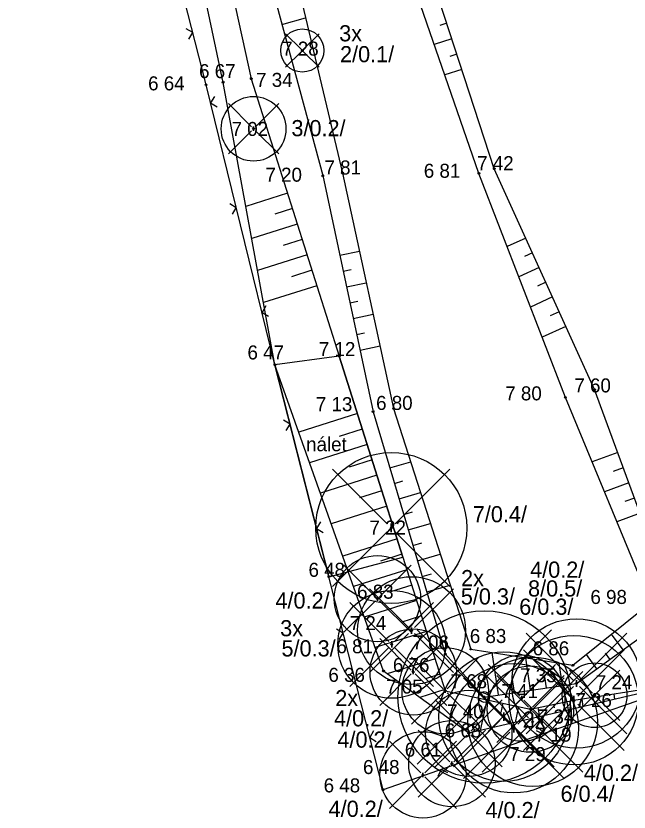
# Model space of a CAD drawing. Extents: x -684336 to -684039, y -993109 to -992688.
# Drawn here: x -684280.1 to -684251.69, y -992904.14 to -992867.21 of the extents above; entities that cross this region are included whole.
import ezdxf

# ---------------------------------------------------------------- set-up
doc = ezdxf.new("R2010")
doc.units = 0
for name, color, linetype in [('51', 7, 'Continuous'), ('57', 7, 'Continuous'), ('60', 7, 'Continuous'), ('70', 7, 'Continuous')]:
    doc.layers.add(name, color=color, linetype=linetype)

msp = doc.modelspace()

# ---------------------------------------------------------------- linework, layer by layer
at = {"layer": '51'}
for points in [[(-684227.21, -992890.21), (-684237.13, -992893.77), (-684248.6, -992898.04), (-684263.09, -992903.1), (-684268.1, -992883.39), (-684271.29, -992870.41), (-684274.7, -992857.04), (-684277.74, -992844.67), (-684280.1, -992835.85), (-684277.64, -992831.2), (-684264.34, -992827.86), (-684252.53, -992824.88)], [(-684248.6, -992898.04), (-684259.12, -992900.48), (-684263.07, -992897.6), (-684268.1, -992883.39), (-684270.5, -992870.3), (-684273.42, -992856.49), (-684276.84, -992844.62), (-684278.77, -992835.66), (-684276.49, -992831.3), (-684269.75, -992830.75), (-684275.57, -992832.23), (-684276.67, -992834.45), (-684274.82, -992844.3), (-684272.25, -992856.25), (-684269.2, -992870.13), (-684265.12, -992882.99), (-684260.21, -992898.51), (-684256.26, -992899.36), (-684254.25, -992898.95), (-684248.751, -992898.075)], [(-684272.088, -992868.292), (-684271.908, -992867.988), (-684272.212, -992867.807)], [(-684270.9, -992870.949), (-684271.083, -992871.251), (-684270.781, -992871.434)], [(-684270.073, -992876.409), (-684269.89, -992876.107), (-684270.192, -992875.924)], [(-684268.514, -992880.66), (-684268.697, -992880.962), (-684268.394, -992881.145)], [(-684267.582, -992886.443), (-684267.401, -992886.139), (-684267.705, -992885.959)], [(-684265.989, -992890.681), (-684266.169, -992890.985), (-684265.866, -992891.166)], [(-684265.118, -992896.135), (-684264.938, -992895.831), (-684265.242, -992895.65)], [(-684255.999, -992900.359), (-684255.681, -992900.513), (-684255.527, -992900.194)], [(-684263.525, -992900.373), (-684263.706, -992900.677), (-684263.402, -992900.858)], [(-684260.083, -992902.315), (-684260.401, -992902.161), (-684260.555, -992902.479)]]:
    msp.add_lwpolyline(points, dxfattribs=at)
for points in [[(-684268.27, -992833.23), (-684270.44, -992832.08), (-684274.11, -992832.95), (-684275.43, -992835.26), (-684273, -992846.66), (-684269.84, -992859.98), (-684265.88, -992874.62), (-684263.55, -992885.57), (-684260.21, -992896.8), (-684258.4, -992898.8), (-684254.13, -992898.17), (-684249.51, -992894.83), (-684253.29, -992884.54), (-684257.94, -992874.3), (-684263.02, -992858.7), (-684266.06, -992847.54)], [(-684269.72, -992835.11), (-684273.83, -992835.79), (-684272.03, -992846.57), (-684268.48, -992859.73), (-684264.97, -992874.5), (-684262.6, -992885.42), (-684259.03, -992896.58), (-684254.29, -992897.33), (-684250.7, -992894.43), (-684254.64, -992884.91), (-684258.65, -992874.52), (-684264.18, -992858.51), (-684267.32, -992848.18)]]:
    msp.add_lwpolyline(points, close=True, dxfattribs=at)
at = {"layer": '57'}
for points in [[(-684266.807, -992868.782), (-684266.785, -992868.82), (-684266.807, -992868.857), (-684266.852, -992868.857), (-684266.875, -992868.82), (-684266.852, -992868.782)], [(-684271.268, -992870.373), (-684271.245, -992870.41), (-684271.268, -992870.448), (-684271.312, -992870.448), (-684271.335, -992870.41), (-684271.312, -992870.373)], [(-684270.478, -992870.263), (-684270.455, -992870.3), (-684270.478, -992870.338), (-684270.522, -992870.338), (-684270.545, -992870.3), (-684270.522, -992870.263)], [(-684269.177, -992870.093), (-684269.155, -992870.13), (-684269.177, -992870.167), (-684269.222, -992870.167), (-684269.245, -992870.13), (-684269.222, -992870.093)], [(-684269.068, -992872.412), (-684269.045, -992872.45), (-684269.068, -992872.487), (-684269.113, -992872.487), (-684269.135, -992872.45), (-684269.113, -992872.412)], [(-684264.948, -992874.463), (-684264.925, -992874.5), (-684264.948, -992874.537), (-684264.992, -992874.537), (-684265.015, -992874.5), (-684264.992, -992874.463)], [(-684258.628, -992874.483), (-684258.605, -992874.52), (-684258.628, -992874.557), (-684258.673, -992874.557), (-684258.695, -992874.52), (-684258.673, -992874.483)], [(-684257.917, -992874.263), (-684257.895, -992874.3), (-684257.917, -992874.338), (-684257.962, -992874.338), (-684257.985, -992874.3), (-684257.962, -992874.263)], [(-684265.858, -992874.583), (-684265.835, -992874.62), (-684265.858, -992874.657), (-684265.903, -992874.657), (-684265.925, -992874.62), (-684265.903, -992874.583)], [(-684265.097, -992882.952), (-684265.075, -992882.99), (-684265.097, -992883.027), (-684265.142, -992883.027), (-684265.165, -992882.99), (-684265.142, -992882.952)], [(-684268.077, -992883.353), (-684268.055, -992883.39), (-684268.077, -992883.427), (-684268.122, -992883.427), (-684268.145, -992883.39), (-684268.122, -992883.353)], [(-684253.268, -992884.503), (-684253.245, -992884.54), (-684253.268, -992884.578), (-684253.312, -992884.578), (-684253.335, -992884.54), (-684253.312, -992884.503)], [(-684254.617, -992884.873), (-684254.595, -992884.91), (-684254.617, -992884.948), (-684254.662, -992884.948), (-684254.685, -992884.91), (-684254.662, -992884.873)], [(-684263.528, -992885.532), (-684263.505, -992885.57), (-684263.528, -992885.607), (-684263.573, -992885.607), (-684263.595, -992885.57), (-684263.573, -992885.532)], [(-684262.577, -992885.383), (-684262.555, -992885.42), (-684262.577, -992885.458), (-684262.622, -992885.458), (-684262.645, -992885.42), (-684262.622, -992885.383)], [(-684262.688, -992890.922), (-684262.665, -992890.96), (-684262.688, -992890.997), (-684262.732, -992890.997), (-684262.755, -992890.96), (-684262.732, -992890.922)], [(-684265.578, -992893.187), (-684265.555, -992893.225), (-684265.578, -992893.262), (-684265.623, -992893.262), (-684265.645, -992893.225), (-684265.623, -992893.187)], [(-684263.327, -992894.202), (-684263.305, -992894.24), (-684263.327, -992894.277), (-684263.372, -992894.277), (-684263.395, -992894.24), (-684263.372, -992894.202)], [(-684261.748, -992895.682), (-684261.725, -992895.72), (-684261.748, -992895.758), (-684261.792, -992895.758), (-684261.815, -992895.72), (-684261.792, -992895.682)], [(-684262.667, -992896.323), (-684262.645, -992896.36), (-684262.667, -992896.397), (-684262.712, -992896.397), (-684262.735, -992896.36), (-684262.712, -992896.323)], [(-684259.008, -992896.542), (-684258.985, -992896.58), (-684259.008, -992896.617), (-684259.052, -992896.617), (-684259.075, -992896.58), (-684259.052, -992896.542)], [(-684260.188, -992896.763), (-684260.165, -992896.8), (-684260.188, -992896.838), (-684260.232, -992896.838), (-684260.255, -992896.8), (-684260.232, -992896.763)], [(-684254.268, -992897.292), (-684254.245, -992897.33), (-684254.268, -992897.367), (-684254.312, -992897.367), (-684254.335, -992897.33), (-684254.312, -992897.292)], [(-684263.047, -992897.562), (-684263.025, -992897.6), (-684263.047, -992897.638), (-684263.093, -992897.638), (-684263.115, -992897.6), (-684263.093, -992897.562)], [(-684261.667, -992897.603), (-684261.645, -992897.64), (-684261.667, -992897.677), (-684261.712, -992897.677), (-684261.735, -992897.64), (-684261.712, -992897.603)], [(-684260.188, -992898.473), (-684260.165, -992898.51), (-684260.188, -992898.548), (-684260.232, -992898.548), (-684260.255, -992898.51), (-684260.232, -992898.473)], [(-684254.108, -992898.133), (-684254.085, -992898.17), (-684254.108, -992898.208), (-684254.153, -992898.208), (-684254.175, -992898.17), (-684254.153, -992898.133)], [(-684258.378, -992898.763), (-684258.355, -992898.8), (-684258.378, -992898.838), (-684258.423, -992898.838), (-684258.445, -992898.8), (-684258.423, -992898.763)], [(-684256.638, -992898.812), (-684256.615, -992898.85), (-684256.638, -992898.888), (-684256.682, -992898.888), (-684256.705, -992898.85), (-684256.682, -992898.812)], [(-684253.268, -992898.682), (-684253.245, -992898.72), (-684253.268, -992898.758), (-684253.312, -992898.758), (-684253.335, -992898.72), (-684253.312, -992898.682)], [(-684254.228, -992898.912), (-684254.205, -992898.95), (-684254.228, -992898.987), (-684254.272, -992898.987), (-684254.295, -992898.95), (-684254.272, -992898.912)], [(-684256.238, -992899.323), (-684256.215, -992899.36), (-684256.238, -992899.397), (-684256.282, -992899.397), (-684256.305, -992899.36), (-684256.282, -992899.323)], [(-684257.478, -992899.672), (-684257.455, -992899.71), (-684257.478, -992899.747), (-684257.522, -992899.747), (-684257.545, -992899.71), (-684257.522, -992899.672)], [(-684256.138, -992899.912), (-684256.115, -992899.95), (-684256.138, -992899.987), (-684256.182, -992899.987), (-684256.205, -992899.95), (-684256.182, -992899.912)], [(-684257.008, -992900.213), (-684256.985, -992900.25), (-684257.008, -992900.287), (-684257.052, -992900.287), (-684257.075, -992900.25), (-684257.052, -992900.213)], [(-684259.097, -992900.443), (-684259.075, -992900.48), (-684259.097, -992900.518), (-684259.142, -992900.518), (-684259.165, -992900.48), (-684259.142, -992900.443)], [(-684259.878, -992901.853), (-684259.855, -992901.89), (-684259.878, -992901.927), (-684259.923, -992901.927), (-684259.945, -992901.89), (-684259.923, -992901.853)], [(-684261.218, -992902.373), (-684261.195, -992902.41), (-684261.218, -992902.448), (-684261.263, -992902.448), (-684261.285, -992902.41), (-684261.263, -992902.373)], [(-684263.068, -992903.062), (-684263.045, -992903.1), (-684263.068, -992903.138), (-684263.113, -992903.138), (-684263.135, -992903.1), (-684263.113, -992903.062)]]:
    msp.add_lwpolyline(points, close=True, dxfattribs=at)
at = {"layer": '60'}
for points in [[(-684266.876, -992868.774), (-684267.608, -992868.042)], [(-684266.784, -992868.774), (-684266.052, -992868.042)], [(-684266.876, -992868.866), (-684267.608, -992869.598)], [(-684266.83, -992868.77), (-684266.83, -992868.87), (-684266.83, -992868.77)], [(-684266.784, -992868.866), (-684266.052, -992869.598)], [(-684269.182, -992872.358), (-684270.257, -992871.283)], [(-684268.998, -992872.358), (-684267.923, -992871.283)], [(-684269.182, -992872.542), (-684270.257, -992873.617)], [(-684269.09, -992872.35), (-684269.09, -992872.55), (-684269.09, -992872.35)], [(-684268.998, -992872.542), (-684267.923, -992873.617)], [(-684262.894, -992890.776), (-684265.432, -992888.238)], [(-684262.526, -992890.776), (-684259.988, -992888.238)], [(-684262.71, -992890.76), (-684262.71, -992891.16), (-684262.71, -992890.76)], [(-684262.894, -992891.144), (-684265.432, -992893.682)], [(-684262.526, -992891.144), (-684259.988, -992893.682)], [(-684263.442, -992894.148), (-684264.906, -992892.684)], [(-684263.258, -992894.148), (-684261.794, -992892.684)], [(-684261.908, -992895.582), (-684263.715, -992893.775)], [(-684261.632, -992895.582), (-684259.825, -992893.775)], [(-684263.442, -992894.332), (-684264.906, -992895.796)], [(-684262.828, -992896.222), (-684264.635, -992894.415)], [(-684263.35, -992894.14), (-684263.35, -992894.34), (-684263.35, -992894.14)], [(-684263.258, -992894.332), (-684261.794, -992895.796)], [(-684262.552, -992896.222), (-684260.745, -992894.415)], [(-684261.908, -992895.858), (-684263.715, -992897.665)], [(-684261.77, -992895.57), (-684261.77, -992895.87), (-684261.77, -992895.57)], [(-684261.632, -992895.858), (-684259.825, -992897.665)], [(-684258.63, -992898.57), (-684261.511, -992895.689)], [(-684258.17, -992898.57), (-684255.289, -992895.689)], [(-684254.268, -992898.032), (-684256.463, -992895.837)], [(-684253.992, -992898.032), (-684251.797, -992895.837)], [(-684261.782, -992897.548), (-684263.246, -992896.084)], [(-684262.69, -992896.21), (-684262.69, -992896.51), (-684262.69, -992896.21)], [(-684261.598, -992897.548), (-684260.134, -992896.084)], [(-684262.828, -992896.498), (-684264.635, -992898.305)], [(-684262.552, -992896.498), (-684260.745, -992898.305)], [(-684254.434, -992898.766), (-684256.583, -992896.617)], [(-684254.066, -992898.766), (-684251.917, -992896.617)], [(-684260.302, -992898.418), (-684261.766, -992896.954)], [(-684260.118, -992898.418), (-684258.654, -992896.954)], [(-684257.684, -992899.526), (-684259.833, -992897.377)], [(-684256.752, -992898.758), (-684258.216, -992897.294)], [(-684257.316, -992899.526), (-684255.167, -992897.377)], [(-684256.568, -992898.758), (-684255.104, -992897.294)], [(-684261.782, -992897.732), (-684263.246, -992899.196)], [(-684261.69, -992897.54), (-684261.69, -992897.74), (-684261.69, -992897.54)], [(-684261.598, -992897.732), (-684260.134, -992899.196)], [(-684256.344, -992899.766), (-684258.493, -992897.617)], [(-684255.976, -992899.766), (-684253.827, -992897.617)], [(-684253.382, -992898.628), (-684254.457, -992897.553)], [(-684253.198, -992898.628), (-684252.123, -992897.553)], [(-684257.214, -992900.066), (-684259.363, -992897.917)], [(-684256.352, -992899.268), (-684257.816, -992897.804)], [(-684256.846, -992900.066), (-684254.697, -992897.917)], [(-684256.168, -992899.268), (-684254.704, -992897.804)], [(-684254.13, -992898.02), (-684254.13, -992898.32), (-684254.13, -992898.02)], [(-684260.21, -992898.41), (-684260.21, -992898.61), (-684260.21, -992898.41)], [(-684254.268, -992898.308), (-684256.463, -992900.503)], [(-684253.992, -992898.308), (-684251.797, -992900.503)], [(-684260.302, -992898.602), (-684261.766, -992900.066)], [(-684260.118, -992898.602), (-684258.654, -992900.066)], [(-684256.66, -992898.75), (-684256.66, -992898.95), (-684256.66, -992898.75)], [(-684253.382, -992898.812), (-684254.457, -992899.887)], [(-684254.25, -992898.75), (-684254.25, -992899.15), (-684254.25, -992898.75)], [(-684253.29, -992898.62), (-684253.29, -992898.82), (-684253.29, -992898.62)], [(-684253.198, -992898.812), (-684252.123, -992899.887)], [(-684258.63, -992899.03), (-684261.511, -992901.911)], [(-684259.212, -992900.388), (-684260.676, -992898.924)], [(-684259.028, -992900.388), (-684257.564, -992898.924)], [(-684256.752, -992898.942), (-684258.216, -992900.406)], [(-684258.17, -992899.03), (-684255.289, -992901.911)], [(-684254.434, -992899.134), (-684256.583, -992901.283)], [(-684256.568, -992898.942), (-684255.104, -992900.406)], [(-684254.066, -992899.134), (-684251.917, -992901.283)], [(-684256.352, -992899.452), (-684257.816, -992900.916)], [(-684257.5, -992899.51), (-684257.5, -992899.91), (-684257.5, -992899.51)], [(-684256.26, -992899.26), (-684256.26, -992899.46), (-684256.26, -992899.26)], [(-684256.168, -992899.452), (-684254.704, -992900.916)], [(-684257.684, -992899.894), (-684259.833, -992902.043)], [(-684257.316, -992899.894), (-684255.167, -992902.043)], [(-684256.16, -992899.75), (-684256.16, -992900.15), (-684256.16, -992899.75)], [(-684259.992, -992901.798), (-684261.456, -992900.334)], [(-684259.808, -992901.798), (-684258.344, -992900.334)], [(-684256.344, -992900.134), (-684258.493, -992902.283)], [(-684257.03, -992900.05), (-684257.03, -992900.45), (-684257.03, -992900.05)], [(-684255.976, -992900.134), (-684253.827, -992902.283)], [(-684259.212, -992900.572), (-684260.676, -992902.036)], [(-684257.214, -992900.434), (-684259.363, -992902.583)], [(-684259.12, -992900.38), (-684259.12, -992900.58), (-684259.12, -992900.38)], [(-684259.028, -992900.572), (-684257.564, -992902.036)], [(-684256.846, -992900.434), (-684254.697, -992902.583)], [(-684261.332, -992902.318), (-684262.796, -992900.854)], [(-684261.148, -992902.318), (-684259.684, -992900.854)], [(-684259.9, -992901.79), (-684259.9, -992901.99), (-684259.9, -992901.79)], [(-684259.992, -992901.982), (-684261.456, -992903.446)], [(-684259.808, -992901.982), (-684258.344, -992903.446)], [(-684261.332, -992902.502), (-684262.796, -992903.966)], [(-684261.24, -992902.31), (-684261.24, -992902.51), (-684261.24, -992902.31)], [(-684261.148, -992902.502), (-684259.684, -992903.966)]]:
    msp.add_lwpolyline(points, dxfattribs=at)
msp.add_lwpolyline([(-684265.6, -992893.225), (-684262.171, -992892.311), (-684265.12, -992882.99), (-684268.1, -992883.39)], close=True, dxfattribs=at)
for centre, radius in [((-684266.83, -992868.82), 1), ((-684269.09, -992872.45), 1.5), ((-684262.71, -992890.96), 3.5), ((-684263.35, -992894.24), 2), ((-684261.77, -992895.72), 2.5), ((-684262.69, -992896.36), 2.5), ((-684258.4, -992898.8), 4), ((-684254.13, -992898.17), 3), ((-684261.69, -992897.64), 2), ((-684254.25, -992898.95), 3), ((-684260.21, -992898.51), 2), ((-684257.5, -992899.71), 3), ((-684256.16, -992899.95), 3), ((-684256.66, -992898.85), 2), ((-684257.03, -992900.25), 3), ((-684256.26, -992899.36), 2), ((-684253.29, -992898.72), 1.5), ((-684259.12, -992900.48), 2), ((-684258.4, -992898.8), 0.25), ((-684259.9, -992901.89), 2), ((-684261.24, -992902.41), 2)]:
    msp.add_circle(centre, radius, dxfattribs=at)
at = {"layer": '70'}
for points in [[(-684267.777, -992867.608), (-684266.678, -992867.311)], [(-684260.135, -992867.558), (-684260.466, -992867.666)], [(-684259.903, -992868.271), (-684260.717, -992868.536)], [(-684259.671, -992868.984), (-684259.991, -992869.089)], [(-684259.439, -992869.698), (-684260.227, -992869.954)], [(-684267.516, -992875.437), (-684269.446, -992876.049)], [(-684267.289, -992876.152), (-684268.097, -992876.408)], [(-684267.063, -992876.867), (-684269.173, -992877.537)], [(-684266.836, -992877.582), (-684267.716, -992877.861)], [(-684256.479, -992877.517), (-684257.342, -992877.909)], [(-684265.094, -992878.315), (-684264.184, -992878.121)], [(-684266.609, -992878.297), (-684268.901, -992879.024)], [(-684256.169, -992878.2), (-684256.53, -992878.364)], [(-684255.859, -992878.883), (-684256.801, -992879.311)], [(-684266.382, -992879.012), (-684267.335, -992879.314)], [(-684264.938, -992879.048), (-684264.573, -992878.971)], [(-684264.782, -992879.782), (-684263.866, -992879.587)], [(-684255.549, -992879.566), (-684255.941, -992879.744)], [(-684266.155, -992879.726), (-684268.628, -992880.511)], [(-684255.239, -992880.249), (-684256.26, -992880.713)], [(-684264.626, -992880.515), (-684264.258, -992880.437)], [(-684264.469, -992881.249), (-684263.548, -992881.053)], [(-684254.928, -992880.932), (-684255.353, -992881.125)], [(-684254.618, -992881.615), (-684255.719, -992882.115)], [(-684264.313, -992881.983), (-684263.943, -992881.904)], [(-684264.157, -992882.716), (-684263.23, -992882.519)], [(-684264.276, -992885.658), (-684266.993, -992886.517)], [(-684264.05, -992886.373), (-684265.127, -992886.714)], [(-684263.824, -992887.088), (-684266.492, -992887.932)], [(-684252.217, -992887.461), (-684253.404, -992887.897)], [(-684263.597, -992887.803), (-684264.655, -992888.138)], [(-684262.775, -992888.177), (-684261.81, -992887.89)], [(-684263.371, -992888.518), (-684265.991, -992889.347)], [(-684251.959, -992888.165), (-684252.422, -992888.335)], [(-684262.561, -992888.896), (-684262.169, -992888.779)], [(-684251.7, -992888.869), (-684252.83, -992889.284)], [(-684263.145, -992889.233), (-684264.183, -992889.562)], [(-684262.347, -992889.615), (-684261.353, -992889.319)], [(-684251.441, -992889.573), (-684251.882, -992889.734)], [(-684262.919, -992889.948), (-684265.49, -992890.762)], [(-684262.133, -992890.334), (-684261.73, -992890.214)], [(-684251.183, -992890.277), (-684252.256, -992890.671)], [(-684261.919, -992891.053), (-684260.896, -992890.748)], [(-684262.439, -992891.464), (-684264.96, -992892.261)], [(-684261.706, -992891.771), (-684261.29, -992891.648)], [(-684262.213, -992892.179), (-684263.212, -992892.495)], [(-684261.492, -992892.49), (-684260.438, -992892.177)], [(-684261.987, -992892.894), (-684264.459, -992893.676)], [(-684261.278, -992893.209), (-684260.851, -992893.082)], [(-684261.761, -992893.609), (-684262.74, -992893.919)], [(-684261.064, -992893.928), (-684259.981, -992893.606)], [(-684261.534, -992894.324), (-684263.958, -992895.091)], [(-684261.308, -992895.039), (-684262.268, -992895.343)], [(-684261.082, -992895.754), (-684263.457, -992896.506)], [(-684251.971, -992896.609), (-684252.497, -992895.882)], [(-684257.743, -992898.703), (-684258.033, -992896.738)], [(-684256.259, -992898.484), (-684256.48, -992896.983)], [(-684253.187, -992897.488), (-684253.666, -992896.826)], [(-684252.579, -992897.049), (-684252.78, -992896.771)], [(-684260.679, -992897.026), (-684262.896, -992897.727)], [(-684254.775, -992898.265), (-684254.928, -992897.229)], [(-684260.453, -992897.741), (-684261.129, -992897.955)], [(-684257.001, -992898.594), (-684257.103, -992897.9)], [(-684255.517, -992898.375), (-684255.592, -992897.867)], [(-684260.227, -992898.456), (-684261.391, -992898.824)], [(-684253.145, -992898.774), (-684253.125, -992898.898)], [(-684252.404, -992898.656), (-684252.364, -992898.913)], [(-684258.278, -992898.926), (-684258.586, -992900.356)], [(-684257.545, -992899.083), (-684257.639, -992899.518)], [(-684255.19, -992899.142), (-684255.157, -992899.305)], [(-684254.455, -992898.992), (-684254.376, -992899.38)], [(-684253.886, -992898.892), (-684253.828, -992899.253)], [(-684256.812, -992899.241), (-684256.971, -992899.982)], [(-684255.925, -992899.292), (-684255.838, -992899.719)]]:
    msp.add_lwpolyline(points, dxfattribs=at)

# ---------------------------------------------------------------- texts
at = {"layer": '57'}
for s, p in [('7 28', (-684267.764, -992869.057)), ('6 67', (-684271.615, -992870.1)), ('6 64', (-684273.976, -992870.666)), ('7 34', (-684268.973, -992870.505)), ('7 02', (-684270.109, -992872.782)), ('7 42', (-684258.73, -992874.368)), ('7 81', (-684265.804, -992874.568)), ('6 81', (-684261.202, -992874.72)), ('7 20', (-684268.539, -992874.903)), ('6 47', (-684269.372, -992883.145)), ('7 12', (-684266.064, -992882.99)), ('7 60', (-684254.226, -992884.675)), ('7 80', (-684257.427, -992885.042)), ('6 80', (-684263.412, -992885.486)), ('7 13', (-684266.204, -992885.544)), ('7 22', (-684263.719, -992891.268)), ('6 48', (-684266.544, -992893.225)), ('6 83', (-684264.294, -992894.24)), ('6 98', (-684253.482, -992894.485)), ('7 24', (-684264.635, -992895.695)), ('6 83', (-684259.069, -992896.295)), ('6 81', (-684265.25, -992896.77)), ('7 06', (-684261.727, -992896.595)), ('6 86', (-684256.156, -992896.866)), ('6 76', (-684262.634, -992897.64)), ('6 36', (-684265.623, -992898.096)), ('7 68', (-684259.964, -992898.393)), ('7 35', (-684256.74, -992898.116)), ('7 05', (-684262.95, -992898.641)), ('7 24', (-684253.233, -992898.442)), ('7 41', (-684257.604, -992898.85)), ('7 26', (-684254.179, -992899.269)), ('7 40', (-684260.121, -992899.793)), ('7 34', (-684255.92, -992900.028)), ('6 68', (-684260.231, -992900.672)), ('7 19', (-684256.046, -992900.87)), ('6 61', (-684262.081, -992901.565)), ('7 29', (-684257.244, -992901.772)), ('6 48', (-684264.019, -992902.371)), ('6 48', (-684265.842, -992903.222))]:
    msp.add_text(s, height=0.65, dxfattribs=at).set_placement(p)
at = {"layer": '60'}
for s, height, p in [('3x', 0.75, (-684265.122, -992868.395)), ('2/0.1/', 0.75, (-684265.083, -992869.363)), ('3/0.2/', 0.75, (-684267.336, -992872.793)), ('nálet', 0.65, (-684266.655, -992887.402)), ('7/0.4/', 0.75, (-684258.93, -992890.696)), ('4/0.2/', 0.75, (-684256.274, -992893.268)), ('2x', 0.75, (-684259.474, -992893.66)), ('8/0.5/', 0.75, (-684256.37, -992894.139)), ('4/0.2/', 0.75, (-684268.076, -992894.698)), ('5/0.3/', 0.75, (-684259.486, -992894.509)), ('6/0.3/', 0.75, (-684256.779, -992894.986)), ('3x', 0.75, (-684267.856, -992895.983)), ('5/0.3/', 0.75, (-684267.795, -992896.918)), ('2x', 0.75, (-684265.304, -992899.223)), ('4/0.2/', 0.75, (-684265.36, -992900.16)), ('2x', 0.75, (-684256.62, -992900.224)), ('4/0.2/', 0.75, (-684265.204, -992901.149)), ('4/0.2/', 0.75, (-684253.788, -992902.687)), ('6/0.4/', 0.75, (-684254.867, -992903.66)), ('4/0.2/', 0.75, (-684265.612, -992904.357)), ('4/0.2/', 0.75, (-684258.345, -992904.417))]:
    msp.add_text(s, height=height, dxfattribs=at).set_placement(p)

doc.saveas('drawing.dxf')
